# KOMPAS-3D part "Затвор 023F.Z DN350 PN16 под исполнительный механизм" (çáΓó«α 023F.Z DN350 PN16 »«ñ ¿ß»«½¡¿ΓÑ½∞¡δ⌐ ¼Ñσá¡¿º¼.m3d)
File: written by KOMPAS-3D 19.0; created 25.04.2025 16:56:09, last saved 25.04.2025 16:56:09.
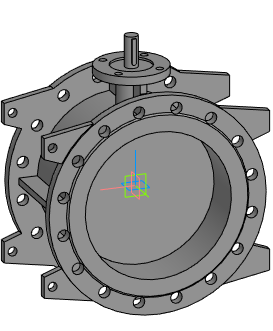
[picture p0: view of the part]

Document properties: Автор: Евгений; Полное имя файла: E:\Dendor Работа Сачек\3D для проекитирвщиков\1.7 Тип 023F.Z Затвор дисковый поворотный фланцевый с двумя эксцентриками\stp_Тип 023F.Z. Затвор под исполн. механизм\Затвор 023F.Z DN350 PN16 под исполнительный механизм.m3d

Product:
- Part/product: Затвор 023F.Z DN350 PN16 под исполнительный механизм

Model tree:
1. Операция без истории:1  (labels: Затвор 023F.Z DN350 PN16 под исполнительный механизм)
